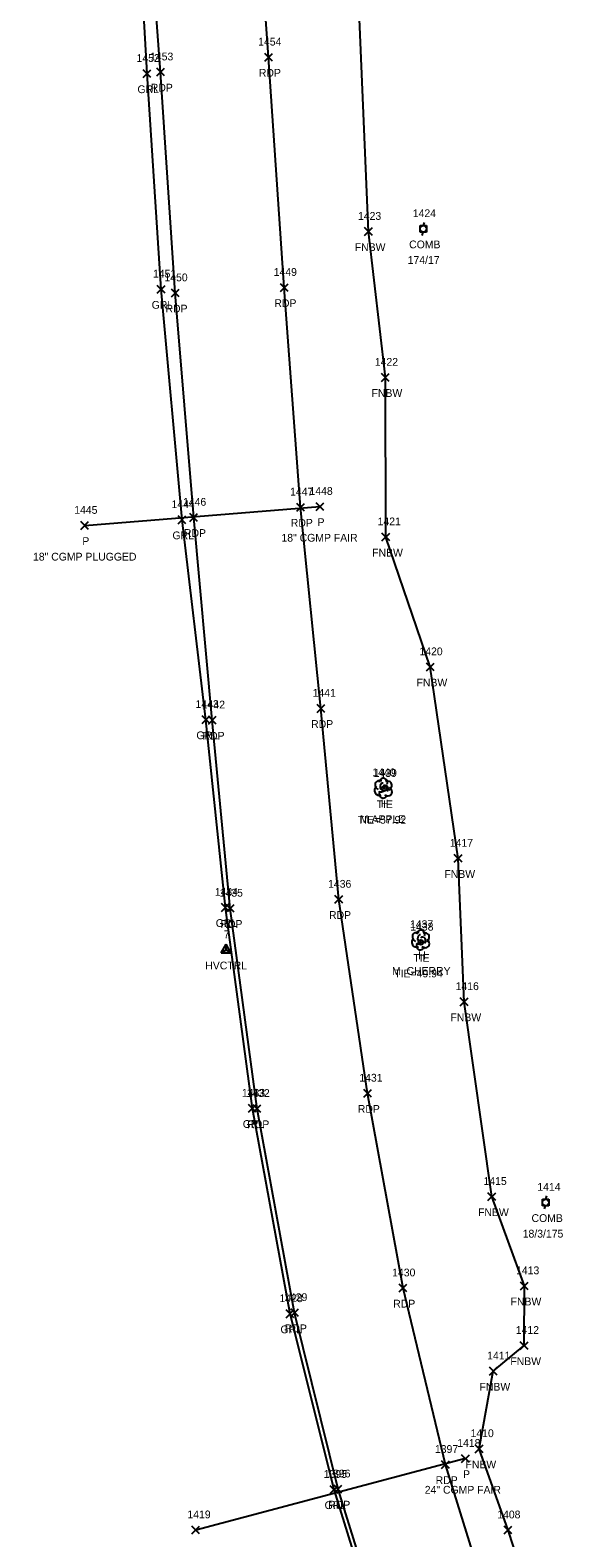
# Model space of a CAD drawing. Extents: x 1503463 to 1505240, y 712171 to 717196.
# Drawn here: x 1503523.8 to 1503661.3, y 715892.8 to 716279.6 of the extents above; entities that cross this region are included whole.
import ezdxf

# ---------------------------------------------------------------- set-up
doc = ezdxf.new("R2010")
doc.units = 0
for name, color, linetype in [('C_A', 7, 'Continuous'), ('C_C', 7, 'Continuous'), ('C_I', 7, 'Continuous'), ('CBP', 7, 'Continuous'), ('CPSM', 7, 'Continuous'), ('D_A', 7, 'Continuous'), ('D_C', 7, 'Continuous'), ('D_I', 7, 'Continuous'), ('D_TIC', 7, 'Continuous'), ('DCP', 7, 'Continuous'), ('L_A', 7, 'Continuous'), ('L_C', 7, 'Continuous'), ('L_I', 7, 'Continuous'), ('L_TIC', 7, 'Continuous'), ('LFNC', 7, 'Continuous'), ('LTD', 7, 'Continuous'), ('P_A', 7, 'Continuous'), ('P_I', 7, 'Continuous'), ('P_TIC', 7, 'Continuous'), ('PET', 7, 'Continuous'), ('R_A', 7, 'Continuous'), ('R_I', 7, 'Continuous'), ('R_TIC', 7, 'Continuous'), ('RGR', 7, 'Continuous'), ('U_A', 7, 'Continuous'), ('U_C', 7, 'Continuous'), ('U_I', 7, 'Continuous'), ('UP', 7, 'Continuous')]:
    doc.layers.add(name, color=color, linetype=linetype)

msp = doc.modelspace()

# ---------------------------------------------------------------- linework, layer by layer
at = {"layer": 'CBP'}
for centre, radius in [((1503614.54, 716085.03), 0.625), ((1503614.54, 716085.03), 0.0833), ((1503623.92, 716045.6), 0.625), ((1503623.92, 716045.6), 0.0833)]:
    msp.add_circle(centre, radius, dxfattribs=at)
at = {"layer": 'CPSM'}
for p, q in [((1503572.76, 716042.93), (1503574.01, 716045.09)), ((1503572.76, 716042.93), (1503574.01, 716043.65)), ((1503572.76, 716042.93), (1503575.26, 716042.93)), ((1503575.26, 716042.93), (1503574.01, 716045.09)), ((1503574.01, 716043.65), (1503574.01, 716045.09)), ((1503574.01, 716043.65), (1503574.01, 716043.65)), ((1503574.01, 716043.65), (1503575.26, 716042.93))]:
    msp.add_line(p, q, dxfattribs=at)
at = {"layer": 'D_TIC'}
for points in [[(1503597.09, 716156.39), (1503599.09, 716158.39)], [(1503599.09, 716156.39), (1503597.09, 716158.39)], [(1503536.81, 716151.54), (1503538.81, 716153.54)], [(1503538.81, 716151.54), (1503536.81, 716153.54)], [(1503634.38, 715912.13), (1503636.38, 715914.13)], [(1503636.38, 715912.13), (1503634.38, 715914.13)], [(1503565.25, 715893.81), (1503567.25, 715895.81)], [(1503567.25, 715893.81), (1503565.25, 715895.81)]]:
    msp.add_lwpolyline(points, dxfattribs=at)
at = {"layer": 'DCP'}
for points in [[(1503537.81, 716152.54), (1503598.09, 716157.39)], [(1503635.38, 715913.13), (1503566.25, 715894.81)]]:
    msp.add_lwpolyline(points, dxfattribs=at)
at = {"layer": 'L_TIC'}
for points in [[(1503609.52, 716226.96), (1503611.52, 716228.96)], [(1503611.52, 716226.96), (1503609.52, 716228.96)], [(1503613.84, 716189.52), (1503615.84, 716191.52)], [(1503615.84, 716189.52), (1503613.84, 716191.52)], [(1503613.98, 716148.58), (1503615.98, 716150.58)], [(1503615.98, 716148.58), (1503613.98, 716150.58)], [(1503625.36, 716115.24), (1503627.36, 716117.24)], [(1503627.36, 716115.24), (1503625.36, 716117.24)], [(1503632.5, 716066.12), (1503634.5, 716068.12)], [(1503634.5, 716066.12), (1503632.5, 716068.12)], [(1503634.04, 716029.34), (1503636.04, 716031.34)], [(1503636.04, 716029.34), (1503634.04, 716031.34)], [(1503641.13, 715979.34), (1503643.13, 715981.34)], [(1503643.13, 715979.34), (1503641.13, 715981.34)], [(1503649.47, 715956.43), (1503651.47, 715958.43)], [(1503651.47, 715956.43), (1503649.47, 715958.43)], [(1503649.4, 715941.12), (1503651.4, 715943.12)], [(1503651.4, 715941.12), (1503649.4, 715943.12)], [(1503641.5, 715934.56), (1503643.5, 715936.56)], [(1503643.5, 715934.56), (1503641.5, 715936.56)], [(1503637.89, 715914.64), (1503639.89, 715916.64)], [(1503639.89, 715914.64), (1503637.89, 715916.64)], [(1503645.28, 715893.79), (1503647.28, 715895.79)], [(1503647.28, 715893.79), (1503645.28, 715895.79)]]:
    msp.add_lwpolyline(points, dxfattribs=at)
at = {"layer": 'LFNC'}
msp.add_lwpolyline([(1503661.34, 715848.63), (1503646.28, 715894.79), (1503638.89, 715915.64), (1503642.5, 715935.56), (1503650.4, 715942.12), (1503650.47, 715957.43), (1503642.13, 715980.34), (1503635.04, 716030.34), (1503633.5, 716067.12), (1503626.36, 716116.24), (1503614.98, 716149.58), (1503614.84, 716190.52), (1503610.52, 716227.96), (1503608.04, 716286.58), (1503598.54, 716329.63), (1503595.1, 716381.31), (1503590.93, 716423.05), (1503582.34, 716496.49), (1503572.76, 716556.17), (1503574.28, 716608.92), (1503572.12, 716660.4)], dxfattribs=at)
at = {"layer": 'LTD'}
for p, q in [((1503614.27, 716085.2), (1503614.27, 716085.2)), ((1503614.27, 716085.2), (1503614.27, 716085.2)), ((1503623.85, 716046.25), (1503623.85, 716046.25)), ((1503623.85, 716046.25), (1503623.85, 716046.25))]:
    msp.add_line(p, q, dxfattribs=at)
for centre in [(1503614.32, 716086.64), (1503623.89, 716047.68)]:
    msp.add_arc(centre, 1.05, 335.5272, 180.9563, dxfattribs=at)
for centre, major_axis, ratio, start_param, end_param in [((1503613.19, 716084.49), (0.58, -1.04), 0.959034, 3.141593, 6.283185), ((1503613.48, 716085.87), (1.21, -0.51), 0.895232, 1.570796, 4.712389), ((1503613.81, 716084.45), (-0.625, -0.083), 0.423636, 0, 3.141593), ((1503614.06, 716085.66), (-0.208, -0.792), 0.645439, 3.141593, 6.283185), ((1503614.77, 716085.04), (-0.5, 0.667), 0.989748, 3.141593, 6.283185), ((1503615.27, 716084.37), (-1.09, 0.79), 0.841452, 1.570796, 4.712389), ((1503615.31, 716085.79), (-1.14, -0.48), 0.949671, 1.570796, 4.712389), ((1503614.27, 716083.7), (0.26, 1.06), 0.942809, 1.570796, 4.712389), ((1503622.76, 716045.54), (0.58, -1.04), 0.959034, 3.141593, 6.283185), ((1503623.05, 716046.92), (1.21, -0.51), 0.895232, 1.570796, 4.712389), ((1503623.39, 716045.5), (-0.625, -0.083), 0.423636, 0, 3.141593), ((1503623.64, 716046.71), (-0.208, -0.792), 0.645439, 3.141593, 6.283185), ((1503624.35, 716046.08), (-0.5, 0.667), 0.989748, 3.141593, 6.283185), ((1503624.85, 716045.42), (-1.09, 0.79), 0.841452, 1.570796, 4.712389), ((1503624.89, 716046.83), (-1.14, -0.48), 0.949671, 1.570796, 4.712389), ((1503623.85, 716044.75), (0.26, 1.06), 0.942809, 1.570796, 4.712389)]:
    msp.add_ellipse(centre, major_axis=major_axis, ratio=ratio, start_param=start_param, end_param=end_param, dxfattribs=at)
at = {"layer": 'P_TIC'}
for points in [[(1503583.94, 716271.68), (1503585.94, 716273.68)], [(1503585.94, 716271.68), (1503583.94, 716273.68)], [(1503556.24, 716267.87), (1503558.24, 716269.87)], [(1503558.24, 716267.87), (1503556.24, 716269.87)], [(1503560.01, 716211.19), (1503562.01, 716213.19)], [(1503562.01, 716211.19), (1503560.01, 716213.19)], [(1503587.93, 716212.58), (1503589.93, 716214.58)], [(1503589.93, 716212.58), (1503587.93, 716214.58)], [(1503592.12, 716156.22), (1503594.12, 716158.22)], [(1503594.12, 716156.22), (1503592.12, 716158.22)], [(1503564.74, 716153.6), (1503566.74, 716155.6)], [(1503566.74, 716153.6), (1503564.74, 716155.6)], [(1503569.5, 716101.59), (1503571.5, 716103.59)], [(1503571.5, 716101.59), (1503569.5, 716103.59)], [(1503597.34, 716104.6), (1503599.34, 716106.6)], [(1503599.34, 716104.6), (1503597.34, 716106.6)], [(1503601.92, 716055.6), (1503603.92, 716057.6)], [(1503603.92, 716055.6), (1503601.92, 716057.6)], [(1503574.08, 716053.31), (1503576.08, 716055.31)], [(1503576.08, 716053.31), (1503574.08, 716055.31)], [(1503609.29, 716005.85), (1503611.29, 716007.85)], [(1503611.29, 716005.85), (1503609.29, 716007.85)], [(1503580.96, 716001.91), (1503582.96, 716003.91)], [(1503582.96, 716001.91), (1503580.96, 716003.91)], [(1503618.37, 715955.88), (1503620.37, 715957.88)], [(1503620.37, 715955.88), (1503618.37, 715957.88)], [(1503590.6, 715949.55), (1503592.6, 715951.55)], [(1503592.6, 715949.55), (1503590.6, 715951.55)], [(1503629.24, 715910.59), (1503631.24, 715912.59)], [(1503631.24, 715910.59), (1503629.24, 715912.59)], [(1503601.71, 715904.3), (1503603.71, 715906.3)], [(1503603.71, 715904.3), (1503601.71, 715906.3)]]:
    msp.add_lwpolyline(points, dxfattribs=at)
at = {"layer": 'PET'}
for points in [[(1503620.07, 715849.48), (1503602.71, 715905.3), (1503591.6, 715950.55), (1503581.96, 716002.91), (1503575.08, 716054.31), (1503570.5, 716102.59), (1503565.74, 716154.6), (1503561.01, 716212.19), (1503557.24, 716268.87), (1503553.18, 716323.39), (1503550.05, 716368.26), (1503546.48, 716421.02), (1503541.51, 716490.14), (1503537.31, 716551.44), (1503534.05, 716602.59), (1503530.11, 716659.58), (1503525.62, 716720.04)], [(1503646.76, 715858.44), (1503630.24, 715911.59), (1503619.37, 715956.88), (1503610.29, 716006.85), (1503602.92, 716056.6), (1503598.34, 716105.6), (1503593.12, 716157.22), (1503588.93, 716213.58), (1503584.94, 716272.68), (1503581.21, 716324.34), (1503578.21, 716369.94), (1503574.51, 716423.14), (1503569.2, 716496.09), (1503565.14, 716552.88), (1503561.64, 716607.83), (1503558.12, 716659.95), (1503553.68, 716721.47)]]:
    msp.add_lwpolyline(points, dxfattribs=at)
at = {"layer": 'R_TIC'}
for points in [[(1503552.78, 716267.47), (1503554.78, 716269.47)], [(1503554.78, 716267.47), (1503552.78, 716269.47)], [(1503556.41, 716212.15), (1503558.41, 716214.15)], [(1503558.41, 716212.15), (1503556.41, 716214.15)], [(1503561.74, 716153), (1503563.74, 716155)], [(1503563.74, 716153), (1503561.74, 716155)], [(1503567.88, 716101.71), (1503569.88, 716103.71)], [(1503569.88, 716101.71), (1503567.88, 716103.71)], [(1503572.84, 716053.53), (1503574.84, 716055.53)], [(1503574.84, 716053.53), (1503572.84, 716055.53)], [(1503579.77, 716001.98), (1503581.77, 716003.98)], [(1503581.77, 716001.98), (1503579.77, 716003.98)], [(1503589.42, 715949.28), (1503591.42, 715951.28)], [(1503591.42, 715949.28), (1503589.42, 715951.28)], [(1503600.73, 715904.18), (1503602.73, 715906.18)], [(1503602.73, 715904.18), (1503600.73, 715906.18)]]:
    msp.add_lwpolyline(points, dxfattribs=at)
at = {"layer": 'RGR'}
msp.add_lwpolyline([(1503619.03, 715849.2), (1503601.73, 715905.18), (1503590.42, 715950.28), (1503580.77, 716002.98), (1503573.84, 716054.53), (1503568.88, 716102.71), (1503562.74, 716154), (1503557.41, 716213.15), (1503553.78, 716268.47), (1503550.62, 716323.9), (1503548.1, 716368.52), (1503543.9, 716420.35), (1503538.97, 716490.86), (1503534.7, 716551.11), (1503531.77, 716602.92), (1503527.84, 716659.98), (1503523.83, 716719.82)], dxfattribs=at)
at = {"layer": 'UP'}
for p, q in [((1503623.73, 716227.82), (1503623.73, 716229.48)), ((1503623.73, 716229.48), (1503625.39, 716229.48)), ((1503625.39, 716227.82), (1503623.73, 716227.82)), ((1503624.31, 716226.98), (1503624.56, 716227.82)), ((1503624.81, 716230.32), (1503624.56, 716229.48)), ((1503624.56, 716228.65), (1503624.56, 716228.65)), ((1503625.39, 716229.48), (1503625.39, 716227.82)), ((1503655.08, 715978.01), (1503655.08, 715979.68)), ((1503655.08, 715979.68), (1503656.75, 715979.68)), ((1503656.16, 715980.51), (1503655.91, 715979.68)), ((1503656.75, 715979.68), (1503656.75, 715978.01)), ((1503656.75, 715978.01), (1503655.08, 715978.01)), ((1503655.66, 715977.18), (1503655.91, 715978.01)), ((1503655.91, 715978.84), (1503655.91, 715978.84))]:
    msp.add_line(p, q, dxfattribs=at)
for centre in [(1503624.56, 716228.65), (1503655.91, 715978.84)]:
    msp.add_circle(centre, 0.833, dxfattribs=at)

# ---------------------------------------------------------------- texts
at = {"layer": 'C_A'}
for s, p in [('TIE', (1503612.62, 716080.03)), ('TIE', (1503622, 716040.6)), ('HVCTRL', (1503568.7, 716038.65))]:
    msp.add_text(s, height=2, dxfattribs=at).set_placement(p)
at = {"layer": 'C_C'}
for s, p in [('TIE=57.92', (1503607.77, 716076.03)), ('TIE=49.94', (1503617.14, 716036.6))]:
    msp.add_text(s, height=2, dxfattribs=at).set_placement(p)
at = {"layer": 'C_I'}
for s, p in [('1439', (1503611.84, 716088.03)), ('1438', (1503621.22, 716048.6)), ('7', (1503573.44, 716046.65))]:
    msp.add_text(s, height=2, dxfattribs=at).set_placement(p)
at = {"layer": 'D_A'}
for p in [(1503597.47, 716152.39), (1503537.19, 716147.54), (1503634.76, 715908.13)]:
    msp.add_text('P', height=2, dxfattribs=at).set_placement(p)
at = {"layer": 'D_C'}
for s, p in [('18" CGMP FAIR', (1503588.21, 716148.39)), ('18" CGMP PLUGGED', (1503524.55, 716143.54)), ('24" CGMP FAIR', (1503624.94, 715904.13))]:
    msp.add_text(s, height=2, dxfattribs=at).set_placement(p)
at = {"layer": 'D_I'}
for s, p in [('1448', (1503595.4, 716160.39)), ('1445', (1503535.12, 716155.54)), ('1418', (1503633.26, 715916.13)), ('1419', (1503564.12, 715897.81))]:
    msp.add_text(s, height=2, dxfattribs=at).set_placement(p)
at = {"layer": 'L_A'}
for s, p in [('FNBW', (1503607, 716222.96)), ('FNBW', (1503611.31, 716185.52)), ('FNBW', (1503611.46, 716144.58)), ('FNBW', (1503622.84, 716111.24)), ('H', (1503613.7, 716080.2)), ('FNBW', (1503629.97, 716062.12)), ('H', (1503623.28, 716041.25)), ('FNBW', (1503631.52, 716025.34)), ('FNBW', (1503638.6, 715975.34)), ('FNBW', (1503646.94, 715952.43)), ('FNBW', (1503646.87, 715937.12)), ('FNBW', (1503638.97, 715930.56)), ('FNBW', (1503635.37, 715910.64))]:
    msp.add_text(s, height=2, dxfattribs=at).set_placement(p)
at = {"layer": 'L_C'}
for s, p in [('M.APPLE', (1503608.33, 716076.2)), ('M. CHERRY', (1503616.54, 716037.25))]:
    msp.add_text(s, height=2, dxfattribs=at).set_placement(p)
at = {"layer": 'L_I'}
for s, p in [('1423', (1503607.83, 716230.96)), ('1422', (1503612.15, 716193.52)), ('1421', (1503612.86, 716152.58)), ('1420', (1503623.58, 716119.24)), ('1440', (1503611.49, 716088.2)), ('1417', (1503631.37, 716070.12)), ('1437', (1503621.15, 716049.25)), ('1416', (1503632.86, 716033.34)), ('1415', (1503640, 715983.34)), ('1413', (1503648.34, 715960.43)), ('1412', (1503648.27, 715945.12)), ('1411', (1503640.94, 715938.56)), ('1410', (1503636.68, 715918.64)), ('1408', (1503643.51, 715897.79))]:
    msp.add_text(s, height=2, dxfattribs=at).set_placement(p)
at = {"layer": 'P_A'}
for p in [(1503582.43, 716267.68), (1503554.73, 716263.87), (1503558.5, 716207.19), (1503586.41, 716208.58), (1503590.61, 716152.22), (1503563.23, 716149.6), (1503567.99, 716097.59), (1503595.82, 716100.6), (1503600.41, 716051.6), (1503572.57, 716049.31), (1503607.78, 716001.85), (1503579.45, 715997.91), (1503616.86, 715951.88), (1503589.09, 715945.55), (1503627.73, 715906.59), (1503600.2, 715900.3)]:
    msp.add_text('RDP', height=2, dxfattribs=at).set_placement(p)
at = {"layer": 'P_I'}
for s, p in [('1454', (1503582.25, 716275.68)), ('1453', (1503554.55, 716271.87)), ('1450', (1503558.23, 716215.19)), ('1449', (1503586.23, 716216.58)), ('1447', (1503590.43, 716160.22)), ('1446', (1503562.99, 716157.6)), ('1442', (1503567.81, 716105.59)), ('1441', (1503596.21, 716108.6)), ('1436', (1503600.17, 716059.6)), ('1435', (1503572.39, 716057.31)), ('1431', (1503608.17, 716009.85)), ('1432', (1503579.27, 716005.91)), ('1430', (1503616.59, 715959.88)), ('1429', (1503588.9, 715953.55)), ('1397', (1503627.55, 715914.59)), ('1396', (1503599.96, 715908.3))]:
    msp.add_text(s, height=2, dxfattribs=at).set_placement(p)
at = {"layer": 'R_A'}
for p in [(1503551.32, 716263.47), (1503554.96, 716208.15), (1503560.29, 716149), (1503566.42, 716097.71), (1503571.38, 716049.53), (1503578.31, 715997.98), (1503587.96, 715945.28), (1503599.27, 715900.18)]:
    msp.add_text('GRL', height=2, dxfattribs=at).set_placement(p)
at = {"layer": 'R_I'}
for s, p in [('1452', (1503551.08, 716271.47)), ('1451', (1503555.29, 716216.15)), ('1444', (1503560.05, 716157)), ('1443', (1503566.19, 716105.71)), ('1434', (1503571.15, 716057.53)), ('1433', (1503578.08, 716005.98)), ('1428', (1503587.72, 715953.28)), ('1395', (1503599.04, 715908.18))]:
    msp.add_text(s, height=2, dxfattribs=at).set_placement(p)
at = {"layer": 'U_A'}
for p in [(1503620.94, 716223.65), (1503652.3, 715973.84)]:
    msp.add_text('COMB', height=2, dxfattribs=at).set_placement(p)
at = {"layer": 'U_C'}
for s, p in [('174/17', (1503620.56, 716219.65)), ('18/3/175', (1503650.04, 715969.84))]:
    msp.add_text(s, height=2, dxfattribs=at).set_placement(p)
at = {"layer": 'U_I'}
for s, p in [('1424', (1503621.87, 716231.65)), ('1414', (1503653.79, 715981.84))]:
    msp.add_text(s, height=2, dxfattribs=at).set_placement(p)

doc.saveas('drawing.dxf')
